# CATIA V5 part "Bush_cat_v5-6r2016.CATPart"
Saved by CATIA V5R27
Part number: Bush
Bounding box of the stored display mesh (mm): x 75 to 115, y 10 to 50, z 160 to 210
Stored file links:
  E:\_Deepak\2017_Deepak\CATIA\Resources\Tutorial Files\Tutorials\c12_catia_v5_6r2015_tut\c12tut2\Bush_cat_v5-6r2016.CATPart
  E:\_Deepak\2017_Deepak\CATIA\Resources\Tutorial Files\Tutorials\c12_catia_v5_6r2015_tut\c12tut2\Assembly_cat_v5-6r2016.CATProduct
  D:\CATIA V5R21 E-RESOURCES\CATIA-V5R21\catia-v5r21-Tut\c12-catia-v5r21-tut\c12-catia-v5r21-tut02\Guide Pillar.CATPart
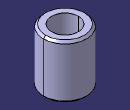
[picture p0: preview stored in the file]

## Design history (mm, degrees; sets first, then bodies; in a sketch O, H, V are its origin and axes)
Set1
  DatumSurface1: linked copy from another document
  DatumCurve1: linked copy from another document
Body1 (main body)
  Sketch1 on face of DatumSurface1, origin (0, 0, 200), H (1, 0, 0), V (0, 1, 0)
    projected circle E1 centre (95, 30) radius 12.5 from edge of DatumCurve1
    circle A1 centre (95, 30) radius 20
    point P1 (95, 30)
    radius A1 = 20
    concentricity: P1 E1, A1 E1
  Pad1: profile Sketch1, direction (0, 0, 1), length 10, opposite side length 40
  Chamfer1: length 2, angle 45, on face of Pad1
